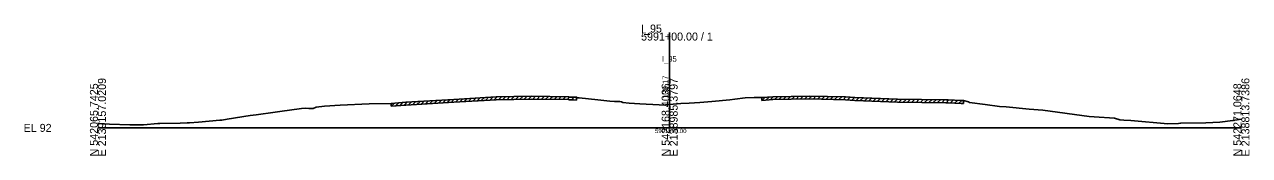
# Model space of a CAD drawing. Extents: x -12534 to 3403, y -1332 to 21983.
# Drawn here: x -25.7 to 402.8, y 18990.3 to 19036.2 of the extents above; entities that cross this region are included whole.
import ezdxf

# ---------------------------------------------------------------- set-up
doc = ezdxf.new("R2010")
doc.units = 0
for name, color, linetype in [('RD_GPK_XS_Cell', 7, 'Continuous'), ('RD_XS_ExGround', 7, 'Continuous'), ('RD_XS_ExPaveRet', 7, 'Continuous'), ('RD_XS_TX_Baseline', 7, 'Continuous'), ('RD_XS_TX_Elev_EX', 7, 'Continuous'), ('RD_XS_TX_Station', 7, 'Continuous')]:
    doc.layers.add(name, color=color, linetype=linetype)

msp = doc.modelspace()

# ---------------------------------------------------------------- linework, layer by layer
at = {"layer": 'RD_GPK_XS_Cell'}
for p, q in [((200, 19000), (200, 19033.4)), ((0, 19000), (200, 19000)), ((200, 19000), (400, 19000))]:
    msp.add_line(p, q, dxfattribs=at)
at = {"layer": 'RD_XS_ExGround'}
msp.add_lwpolyline([(0, 19001.64), (1.34, 19001.45), (2.31, 19001.36), (4.05, 19001.33), (11.14, 19001.06), (14.32, 19001.06), (15.93, 19001.08), (20.94, 19001.49), (21.67, 19001.52), (28.75, 19001.7), (31.26, 19001.74), (32.07, 19001.82), (35.13, 19002.03), (42.61, 19002.71), (43.29, 19002.69), (45.18, 19003.02), (53.24, 19004.32), (55.33, 19004.59), (62.01, 19005.51), (63.65, 19005.73), (71.26, 19006.77), (72.49, 19006.95), (73.72, 19006.81), (75.34, 19006.83), (76.3, 19007.25), (79.24, 19007.59), (84.74, 19007.93), (94.88, 19008.4), (102.61, 19008.58), (107.76, 19009), (124.54, 19010), (139.28, 19010.86), (151.62, 19011.11), (164.64, 19010.92), (164.99, 19010.79), (166.32, 19010.77), (167.46, 19010.73), (167.71, 19010.54), (168.37, 19010.48), (174.82, 19009.8), (179.02, 19009.35), (180.75, 19009.21), (182.47, 19009.3), (183.12, 19009.1), (183.67, 19008.89), (185.82, 19008.69), (189.6, 19008.42), (196.27, 19008.03), (198.13, 19008), (198.57, 19008.05), (200, 19008.17), (203.89, 19008.5), (206.81, 19008.71), (210.5, 19008.94), (214.78, 19009.22), (221.05, 19009.8), (222.78, 19010.02), (226.4, 19010.51), (229.59, 19010.69), (232.2, 19010.61), (236.08, 19010.89), (248.9, 19011.13), (261.54, 19010.85), (264.73, 19010.63), (279.73, 19010.03), (296.59, 19009.79), (297.39, 19009.78), (301.94, 19009.6), (302.8, 19009.55), (304.51, 19009.17), (304.93, 19008.92), (310.41, 19008.18), (315.39, 19007.52), (317.76, 19007.34), (325.73, 19006.6), (330.52, 19006.26), (346.79, 19004), (348.47, 19003.87), (355.63, 19003.46), (357.44, 19002.87), (358.84, 19002.73), (361.33, 19002.56), (374.32, 19001.41), (377.95, 19001.55), (378.8, 19001.7), (387.54, 19001.73), (392.41, 19002.01), (397.01, 19002.61), (400, 19003.02)], dxfattribs=at)
at = {"layer": 'RD_XS_ExPaveRet'}
for p, q in [((119.11, 19008.67), (120.17, 19009.74)), ((120.61, 19008.76), (121.67, 19009.83)), ((122.11, 19008.85), (123.17, 19009.92)), ((123.61, 19008.94), (124.67, 19010.01)), ((124.54, 19009), (139.28, 19009.86)), ((125.11, 19009.03), (126.17, 19010.09)), ((126.61, 19009.12), (127.67, 19010.18)), ((128.11, 19009.21), (129.17, 19010.27)), ((129.61, 19009.29), (130.67, 19010.36)), ((131.11, 19009.38), (132.17, 19010.44)), ((132.61, 19009.47), (133.67, 19010.53)), ((134.11, 19009.56), (135.17, 19010.62)), ((135.61, 19009.65), (136.67, 19010.71)), ((137.11, 19009.73), (138.17, 19010.8)), ((138.61, 19009.82), (139.66, 19010.87)), ((139.28, 19009.86), (151.62, 19010.11)), ((140.11, 19009.88), (141.13, 19010.9)), ((141.61, 19009.91), (142.63, 19010.93)), ((143.11, 19009.94), (144.13, 19010.96)), ((144.61, 19009.97), (145.63, 19010.99)), ((146.11, 19010), (147.13, 19011.02)), ((147.61, 19010.03), (148.63, 19011.05)), ((149.11, 19010.06), (150.13, 19011.08)), ((150.61, 19010.09), (151.63, 19011.11)), ((151.62, 19010.11), (164.64, 19009.92)), ((152.11, 19010.1), (153.09, 19011.09)), ((153.61, 19010.08), (154.59, 19011.07)), ((155.11, 19010.06), (156.09, 19011.04)), ((156.61, 19010.04), (157.59, 19011.02)), ((158.11, 19010.01), (159.09, 19011)), ((159.61, 19009.99), (160.59, 19010.98)), ((161.11, 19009.97), (162.09, 19010.95)), ((162.61, 19009.95), (163.59, 19010.93)), ((164.11, 19009.92), (164.98, 19010.8)), ((164.64, 19009.92), (164.99, 19009.79)), ((164.99, 19009.79), (166.32, 19009.77)), ((165.61, 19009.78), (166.59, 19010.76)), ((166.32, 19009.77), (167.46, 19009.73)), ((167.46, 19010.73), (167.46, 19009.73)), ((232.2, 19009.61), (233.27, 19010.69)), ((232.2, 19009.61), (232.2, 19010.61)), ((232.2, 19009.61), (236.08, 19009.89)), ((233.7, 19009.72), (234.77, 19010.8)), ((235.2, 19009.83), (236.26, 19010.89)), ((236.08, 19009.89), (248.9, 19010.13)), ((236.7, 19009.9), (237.72, 19010.92)), ((238.2, 19009.93), (239.22, 19010.95)), ((239.7, 19009.96), (240.72, 19010.98)), ((241.2, 19009.99), (242.22, 19011)), ((242.7, 19010.01), (243.72, 19011.03)), ((244.2, 19010.04), (245.22, 19011.06)), ((245.7, 19010.07), (246.72, 19011.09)), ((247.2, 19010.1), (248.22, 19011.12)), ((248.7, 19010.13), (249.69, 19011.12)), ((248.9, 19010.13), (261.54, 19009.85)), ((250.2, 19010.1), (251.18, 19011.08)), ((251.7, 19010.07), (252.68, 19011.05)), ((253.2, 19010.04), (254.18, 19011.02)), ((254.7, 19010.01), (255.68, 19010.98)), ((256.2, 19009.97), (257.18, 19010.95)), ((257.7, 19009.94), (258.68, 19010.92)), ((259.2, 19009.91), (260.18, 19010.88)), ((260.7, 19009.87), (261.67, 19010.85)), ((261.54, 19009.85), (264.73, 19009.63)), ((262.2, 19009.81), (263.13, 19010.74)), ((263.7, 19009.7), (264.63, 19010.64)), ((265.2, 19009.61), (266.16, 19010.57)), ((266.7, 19009.55), (267.66, 19010.51)), ((268.2, 19009.49), (269.16, 19010.45)), ((269.7, 19009.43), (270.66, 19010.39)), ((271.2, 19009.37), (272.16, 19010.33)), ((272.7, 19009.31), (273.66, 19010.27)), ((274.2, 19009.25), (275.16, 19010.21)), ((275.7, 19009.19), (276.66, 19010.15)), ((277.2, 19009.13), (278.16, 19010.09)), ((278.7, 19009.07), (279.66, 19010.03)), ((280.2, 19009.02), (281.19, 19010.01)), ((281.7, 19009), (282.69, 19009.99)), ((283.2, 19008.98), (284.19, 19009.97)), ((284.7, 19008.96), (285.69, 19009.95)), ((286.2, 19008.94), (287.19, 19009.93)), ((287.7, 19008.92), (288.69, 19009.91)), ((289.2, 19008.9), (290.19, 19009.88)), ((290.7, 19008.88), (291.69, 19009.86)), ((292.2, 19008.86), (293.19, 19009.84)), ((293.7, 19008.84), (294.69, 19009.82)), ((295.2, 19008.81), (296.19, 19009.8)), ((296.7, 19008.79), (297.68, 19009.77)), ((298.2, 19008.75), (299.16, 19009.71)), ((102.61, 19007.58), (103.7, 19008.67)), ((102.61, 19007.58), (102.61, 19008.58)), ((102.61, 19007.58), (107.76, 19008)), ((104.11, 19007.7), (105.2, 19008.79)), ((105.61, 19007.82), (106.7, 19008.91)), ((107.11, 19007.95), (108.19, 19009.02)), ((107.76, 19008), (124.54, 19009)), ((108.61, 19008.05), (109.67, 19009.11)), ((110.11, 19008.14), (111.17, 19009.2)), ((111.61, 19008.23), (112.67, 19009.29)), ((113.11, 19008.32), (114.17, 19009.38)), ((114.61, 19008.41), (115.67, 19009.47)), ((116.11, 19008.5), (117.17, 19009.56)), ((117.61, 19008.59), (118.67, 19009.65)), ((264.73, 19009.63), (279.73, 19009.03)), ((279.73, 19009.03), (296.59, 19008.79)), ((296.59, 19008.79), (297.39, 19008.78)), ((297.39, 19008.78), (301.94, 19008.6)), ((299.7, 19008.69), (300.66, 19009.65)), ((301.2, 19008.63), (302.16, 19009.59)), ((301.94, 19008.6), (302.8, 19008.55)), ((302.8, 19009.55), (302.8, 19008.55))]:
    msp.add_line(p, q, dxfattribs=at)

# ---------------------------------------------------------------- texts
at = {"layer": 'RD_GPK_XS_Cell'}
for s, p in [('I_95', (190, 19033.4)), ('5991+00.00 / 1', (190, 19030.6)), ('EL 92', (-26, 18998.6))]:
    msp.add_text(s, height=2.8, dxfattribs=at).set_placement(p)
for s, p in [('N 542065.7425', (0, 18990)), ('E 2139157.0209', (2.8, 18990)), ('N 542168.4036', (200, 18990)), ('E 2138985.3797', (202.8, 18990)), ('N 542271.0648', (400, 18990)), ('E 2138813.7386', (402.8, 18990))]:
    msp.add_text(s, height=2.8, rotation=90, dxfattribs=at).set_placement(p)
at = {"layer": 'RD_XS_TX_Baseline'}
msp.add_text('I_95', height=2, dxfattribs=at).set_placement((197.28, 19023.17))
at = {"layer": 'RD_XS_TX_Elev_EX'}
msp.add_text('100.17', height=2, rotation=90, dxfattribs=at).set_placement((199.5, 19010.17))
at = {"layer": 'RD_XS_TX_Station'}
msp.add_text('5991+00.00', height=1.5, dxfattribs=at).set_placement((194.89, 18998.17))

doc.saveas('drawing.dxf')
